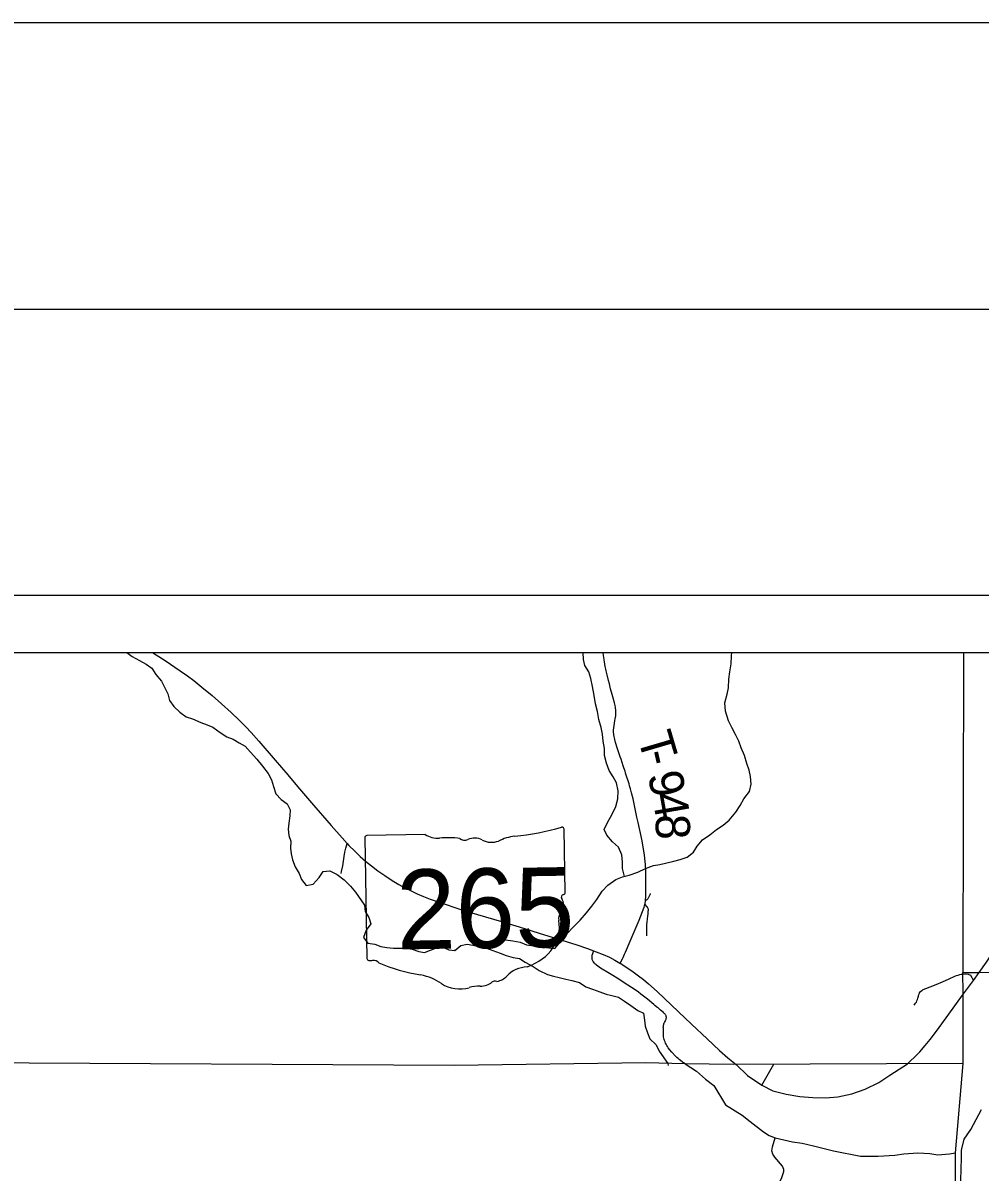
# Model space of a CAD drawing. Extents: x 0 to 2329303, y 0 to 694397.
# Drawn here: x 3.861 to 5.532, y 19.992 to 22 of the extents above; entities that cross this region are included whole.
import ezdxf

# ---------------------------------------------------------------- set-up
doc = ezdxf.new("R2010")
doc.units = 0
for name, color, linetype in [('GM_X_Minor_River', 7, 'Continuous'), ('GM_X_State_Route', 7, 'Continuous'), ('GM_X_State_Shield', 7, 'Continuous'), ('GM_X_Township', 7, 'Continuous'), ('GM_X_Township_Road', 7, 'Continuous'), ('GM_X_Township_Road_Text', 7, 'Continuous'), ('GM_X_Township_ROW', 7, 'Continuous'), ('SH_Border', 7, 'Continuous'), ('SH_Cut_Line', 7, 'Continuous'), ('SH_Data', 7, 'Continuous')]:
    doc.layers.add(name, color=color, linetype=linetype)

msp = doc.modelspace()

# ---------------------------------------------------------------- linework, layer by layer
at = {"layer": 'GM_X_Minor_River'}
for points in [[(4.0425, 20.9), (4.0521, 20.8932), (4.0647, 20.8863), (4.076, 20.8798), (4.0862, 20.8729), (4.0933, 20.8619), (4.1028, 20.8501), (4.1091, 20.8383), (4.1142, 20.8276), (4.1173, 20.8161), (4.1244, 20.8055), (4.1351, 20.7958), (4.1461, 20.7877), (4.1574, 20.784), (4.1715, 20.778), (4.1828, 20.7739), (4.1929, 20.7694), (4.2056, 20.7602), (4.217, 20.7525), (4.2283, 20.7484), (4.2384, 20.7423), (4.249, 20.7362), (4.2584, 20.726), (4.2696, 20.7135), (4.2795, 20.7014), (4.2894, 20.6889), (4.2953, 20.6778), (4.2988, 20.6659), (4.3028, 20.6532), (4.3118, 20.643), (4.3224, 20.6357), (4.3275, 20.6254), (4.327, 20.615), (4.3253, 20.6021)], [(4.6727, 20.3827), (4.6789, 20.3952), (4.6903, 20.4016), (4.704, 20.398), (4.7164, 20.3965), (4.7293, 20.3941), (4.7406, 20.3892), (4.7535, 20.3873), (4.7691, 20.3854), (4.79, 20.3832), (4.8012, 20.3956), (4.8108, 20.4083), (4.8224, 20.4207), (4.834, 20.4323), (4.8452, 20.4451), (4.8544, 20.4566), (4.8632, 20.4685), (4.8728, 20.4832), (4.8824, 20.4935), (4.8965, 20.5036), (4.9084, 20.508), (4.9199, 20.5112), (4.9349, 20.5161), (4.9483, 20.5225), (4.9625, 20.5278), (4.9732, 20.5297), (4.9855, 20.5325), (4.9978, 20.5357), (5.0089, 20.5385), (5.0208, 20.5425), (5.0321, 20.5513), (5.0386, 20.5619), (5.0478, 20.5726), (5.0607, 20.5818), (5.072, 20.5906), (5.0838, 20.5982), (5.0943, 20.6069), (5.1058, 20.6213), (5.1135, 20.6328), (5.1203, 20.6442), (5.1299, 20.6573), (5.1327, 20.6702), (5.1319, 20.6834), (5.1291, 20.6945), (5.1252, 20.706), (5.1211, 20.7199), (5.1155, 20.7333), (5.1111, 20.7452), (5.1056, 20.7566), (5.0992, 20.7692), (5.0932, 20.7806), (5.0879, 20.7976), (5.0871, 20.812), (5.091, 20.8273), (5.093, 20.8386), (5.0941, 20.8535), (5.0957, 20.8663), (5.0977, 20.8804), (5.0985, 20.894), (5.0988, 20.9)], [(4.9115, 20.5089), (4.9083, 20.5228), (4.9083, 20.534), (4.9067, 20.5468), (4.9011, 20.5598), (4.8904, 20.5695), (4.8805, 20.5807), (4.8762, 20.591), (4.8826, 20.604), (4.8894, 20.6166), (4.8965, 20.6313), (4.8997, 20.6446), (4.9004, 20.6582), (4.8976, 20.6725), (4.8917, 20.6828), (4.8849, 20.6937), (4.8801, 20.7068), (4.8765, 20.7199), (4.8765, 20.7323), (4.8745, 20.745), (4.8734, 20.7574), (4.8706, 20.7693), (4.8666, 20.7828), (4.8645, 20.7971), (4.8609, 20.8106), (4.8585, 20.8249), (4.856, 20.8405), (4.8527, 20.8544), (4.8492, 20.8663), (4.8424, 20.8772), (4.8401, 20.8876), (4.8393, 20.9), (4.8393, 20.9)], [(4.3253, 20.6021), (4.324, 20.5913), (4.3255, 20.5805), (4.329, 20.5702), (4.3285, 20.5581), (4.3296, 20.5481), (4.3318, 20.5378), (4.3362, 20.5255), (4.3437, 20.5141), (4.3476, 20.5034), (4.3558, 20.4928), (4.3682, 20.4955), (4.3783, 20.5067), (4.3852, 20.5173), (4.3971, 20.5184), (4.4101, 20.5124), (4.4219, 20.5031), (4.433, 20.4918), (4.4417, 20.4813), (4.4575, 20.4585), (4.459, 20.4477), (4.4653, 20.437), (4.4688, 20.4263), (4.4603, 20.4149), (4.4558, 20.4023), (4.4633, 20.3921), (4.4757, 20.3904), (4.4862, 20.3867), (4.4963, 20.3846), (4.5083, 20.3834), (4.5203, 20.3833), (4.5307, 20.3836), (4.5407, 20.3815), (4.5524, 20.3778), (4.5624, 20.3761), (4.5727, 20.38), (4.5834, 20.384), (4.5946, 20.3855), (4.6051, 20.3806), (4.6151, 20.3793), (4.6139, 20.3792)], [(4.6151, 20.3793), (4.6256, 20.3879), (4.6367, 20.3906), (4.6467, 20.3886), (4.6592, 20.3862), (4.6709, 20.3834), (4.6814, 20.3797), (4.6943, 20.3749), (4.7049, 20.3709), (4.717, 20.3672), (4.7282, 20.3652), (4.7384, 20.3591), (4.7522, 20.3516), (4.7624, 20.3443), (4.777, 20.3376), (4.7875, 20.3347), (4.7976, 20.3323), (4.8093, 20.3294), (4.8197, 20.327), (4.833, 20.3234), (4.8441, 20.3158), (4.8558, 20.3121), (4.8687, 20.307), (4.8796, 20.3033), (4.8897, 20.3008), (4.9014, 20.2976), (4.9116, 20.2908), (4.9226, 20.2831), (4.9349, 20.2747), (4.945, 20.2702), (4.9466, 20.2579), (4.9477, 20.2475), (4.9517, 20.2356), (4.956, 20.225), (4.9671, 20.2145), (4.9719, 20.2035), (4.9875, 20.1818), (4.988, 20.1784)]]:
    msp.add_lwpolyline(points, dxfattribs=at)
at = {"layer": 'GM_X_State_Route'}
for points in [[(4.0875, 20.9), (4.0936, 20.8963), (4.1095, 20.8859), (4.1355, 20.8681), (4.1483, 20.8591), (4.1593, 20.8509), (4.1737, 20.8394), (4.1913, 20.8247), (4.2076, 20.8106), (4.2246, 20.7951), (4.2389, 20.7816), (4.2504, 20.77), (4.2594, 20.7604), (4.2729, 20.7453), (4.3017, 20.7121), (4.3235, 20.6863)], [(4.3235, 20.6863), (4.3407, 20.666), (4.3649, 20.6375), (4.3991, 20.5977), (4.4183, 20.5761), (4.4271, 20.5665), (4.4303, 20.5631), (4.4405, 20.5527), (4.45, 20.5437), (4.4594, 20.5354), (4.4696, 20.5271), (4.4806, 20.5188), (4.493, 20.5102), (4.5057, 20.502), (4.5175, 20.4948), (4.5267, 20.4897), (4.5379, 20.484), (4.5498, 20.4784), (4.5606, 20.4737), (4.5723, 20.4692), (4.5896, 20.4631), (4.624, 20.4519), (4.6409, 20.4465), (4.6968, 20.43), (4.7276, 20.4205), (4.7628, 20.4099), (4.7947, 20.4), (4.8284, 20.3893), (4.8471, 20.3829), (4.8576, 20.379), (4.8624, 20.3772), (4.8745, 20.3723), (4.8853, 20.3675), (4.8946, 20.3628), (4.9036, 20.3575), (4.904, 20.3573), (4.9141, 20.3509), (4.9265, 20.3423), (4.936, 20.3354), (4.9448, 20.3286), (4.9538, 20.3211), (4.9684, 20.3079), (5.0061, 20.2724), (5.0288, 20.2506), (5.0559, 20.2248), (5.0775, 20.2047), (5.0922, 20.1916), (5.1065, 20.18)], [(5.5019, 20.3015), (5.5211, 20.327), (5.5308, 20.3409), (5.5439, 20.3593), (5.5686, 20.3975), (5.6124, 20.4489), (5.6569, 20.5022), (5.6914, 20.5425), (5.7219, 20.5802), (5.7635, 20.6292)], [(5.4059, 20.1814), (5.4095, 20.1848), (5.4199, 20.1949), (5.4272, 20.2025), (5.4367, 20.2134), (5.4455, 20.2241), (5.4563, 20.2382), (5.4779, 20.268), (5.5019, 20.3015)], [(5.1065, 20.18), (5.1265, 20.1609), (5.1512, 20.1442), (5.1705, 20.1342), (5.194, 20.1283), (5.2177, 20.1243), (5.2406, 20.1224), (5.2627, 20.122), (5.2842, 20.124), (5.3084, 20.1289), (5.3317, 20.1374), (5.3557, 20.1487), (5.3749, 20.1618), (5.4059, 20.1814)], [(5.5007, 20.033), (5.5046, 20.0496), (5.5164, 20.0666), (5.5349, 20.1016)], [(5.4896, 19.5547), (5.4963, 19.5711), (5.5005, 19.5907), (5.503, 19.6107), (5.5027, 19.6294), (5.5009, 19.6616), (5.5008, 19.6926), (5.4982, 19.7527), (5.4993, 19.8307), (5.4998, 19.9151), (5.4988, 19.9776), (5.5001, 20.0174), (5.4999, 20.0298), (5.5007, 20.033)]]:
    msp.add_lwpolyline(points, dxfattribs=at)
at = {"layer": 'GM_X_State_Shield'}
for p, q in [((4.5636, 20.5821), (4.4617, 20.5803)), ((4.808, 20.4808), (4.8061, 20.5914)), ((4.4583, 20.5766), (4.4619, 20.3654)), ((4.808, 20.4809), (4.808, 20.4808))]:
    msp.add_line(p, q, dxfattribs=at)
for centre, major_axis, start_param, end_param in [((4.4623, 20.5772), (0.00403, 0.00007), 1.712693, 3.28349), ((4.5874, 20.607), (0.0391, 0.0007), 4.042523, 4.731795), ((4.7304, 20.5203), (0.0742, 0.0012), 1.699011, 2.107814), ((4.6774, 20.8721), (0.369, 0.0062), 4.814394, 5.042369), ((4.8023, 20.5918), (0.00387, 0.00006), 6.141152, 7.989035), ((4.6028, 20.4641), (0.1404, 0.0024), 1.404758, 1.657858), ((4.6327, 20.5811), (0.0113, 0.0002), 3.836095, 5.185415), ((4.6497, 20.557), (0.0235, 0.0004), 0.950623, 2.079405), ((4.6794, 20.591), (0.0282, 0.0005), 4.081561, 5.145723), ((4.8039, 20.4803), (0.00415, 0.00007), 5.05454, 6.418171), ((4.8072, 20.4727), (0.006, 0.0001), 1.883978, 3.671073), ((4.7693, 20.4581), (0.036, 0.0006), 5.934695, 6.695948), ((4.8227, 20.4348), (0.0262, 0.0004), 2.387724, 3.262537), ((4.7057, 20.4188), (0.0923, 0.0015), 5.101752, 6.440018), ((4.4659, 20.365), (0.00407, 0.00007), 3.00124, 4.508301), ((4.4661, 20.3866), (0.031, 0.0005), 4.665946, 4.897461), ((4.473, 20.3533), (0.0112, 0.0002), 0.519207, 1.627899), ((4.6112, 20.5456), (0.2665, 0.0045), 4.195997, 4.488961), ((4.7465, 20.3108), (0.0506, 0.0008), 1.647645, 2.488434), ((4.5363, 20.2716), (0.0834, 0.0014), 0.823519, 1.323587), ((4.6251, 20.3548), (0.0529, 0.0009), 4.026481, 4.996735), ((4.6569, 20.2823), (0.0435, 0.0007), 1.495662, 1.94098), ((4.6598, 20.3396), (0.0282, 0.0005), 4.691044, 5.507374), ((4.6856, 20.3196), (0.00794, 0.00013), 1.147584, 2.315152), ((4.6818, 20.3486), (0.0298, 0.0005), 4.937069, 5.64225)]:
    msp.add_ellipse(centre, major_axis=major_axis, ratio=0.8, start_param=start_param, end_param=end_param, dxfattribs=at)
at = {"layer": 'GM_X_Township'}
msp.add_line((5.5036, 20.9), (5.5027, 20.3409), dxfattribs=at)
for points in [[(5.8223, 14.1123), (5.5, 14.1), (5.5092, 14.6075), (5.4849, 16.2502), (5.4862, 16.3702), (5.4966, 17.3083), (5.484, 18.4012), (5.4927, 19.2711), (5.4941, 19.3381), (5.4896, 19.5547), (5.4893, 19.9096), (5.4898, 20.0261), (5.5032, 20.182), (5.5028, 20.3048), (5.5027, 20.3409), (5.5308, 20.3409), (5.6417, 20.3416)], [(5.5032, 20.182), (5.102, 20.1805), (5.0168, 20.1816), (4.9486, 20.1829), (4.6141, 20.1787), (3.7653, 20.1833), (2.7861, 20.1837), (2.2689, 20.1812), (2.1, 20.1819)]]:
    msp.add_lwpolyline(points, dxfattribs=at)
at = {"layer": 'GM_X_Township_Road'}
for points in [[(4.9483, 20.4669), (4.9487, 20.4742), (4.9489, 20.4827), (4.9491, 20.4991), (4.9491, 20.5103), (4.9488, 20.5214), (4.9485, 20.526), (4.9482, 20.5299), (4.9471, 20.5402), (4.9463, 20.5466), (4.9447, 20.5562), (4.9422, 20.571), (4.9395, 20.5845), (4.9384, 20.5897), (4.9353, 20.6031), (4.9333, 20.6121), (4.9296, 20.6301), (4.9265, 20.6442), (4.924, 20.655), (4.9222, 20.6619), (4.9205, 20.6674), (4.9197, 20.6704), (4.9185, 20.6741), (4.9174, 20.6778), (4.9165, 20.6803), (4.9152, 20.6839), (4.914, 20.6875), (4.9134, 20.6894), (4.9125, 20.6925), (4.9115, 20.6956), (4.9105, 20.6987), (4.9095, 20.7018), (4.9056, 20.7136), (4.9041, 20.7179), (4.8995, 20.7315), (4.8959, 20.7428), (4.8946, 20.7478), (4.8932, 20.7562), (4.8927, 20.7614), (4.8926, 20.7646), (4.8935, 20.7724), (4.8949, 20.7808), (4.8955, 20.784), (4.8962, 20.7892), (4.8966, 20.7944), (4.8965, 20.799), (4.8959, 20.8042), (4.8953, 20.8073), (4.8941, 20.8123), (4.8913, 20.8224), (4.889, 20.8306), (4.8886, 20.8325), (4.8874, 20.8369), (4.8852, 20.8451), (4.8837, 20.8514), (4.8812, 20.8609), (4.8795, 20.8679), (4.8788, 20.8711), (4.8779, 20.8756), (4.8765, 20.8839), (4.876, 20.8872), (4.8753, 20.8917), (4.875, 20.8943), (4.8742, 20.9)], [(4.4167, 20.5138), (4.4176, 20.5176), (4.4195, 20.5273), (4.4219, 20.5435), (4.4233, 20.5513), (4.4251, 20.5583), (4.4271, 20.5665)], [(4.9483, 20.4669), (4.9492, 20.4673), (4.9497, 20.4676), (4.9502, 20.4679), (4.9507, 20.4682), (4.9513, 20.4688), (4.9518, 20.4693), (4.9524, 20.4699), (4.953, 20.4707), (4.9535, 20.4716), (4.957, 20.4786), (4.9573, 20.4792)], [(4.904, 20.3573), (4.9079, 20.3647), (4.9091, 20.367), (4.9119, 20.3729), (4.9135, 20.3765), (4.9218, 20.3958), (4.9268, 20.4079), (4.9335, 20.4241), (4.9372, 20.4325), (4.9403, 20.4402), (4.9431, 20.4475), (4.9457, 20.4552), (4.9465, 20.4576), (4.9472, 20.4603)], [(4.9472, 20.4603), (4.9476, 20.4618), (4.9482, 20.4657), (4.9483, 20.4669)], [(4.9509, 20.4048), (4.9508, 20.4058), (4.9507, 20.4074), (4.9504, 20.414), (4.9504, 20.4185), (4.9507, 20.4243), (4.9512, 20.4295), (4.9517, 20.434), (4.9524, 20.4398), (4.9528, 20.4429), (4.9529, 20.4441), (4.9532, 20.4479), (4.9533, 20.45), (4.9533, 20.4513), (4.9531, 20.4521), (4.9528, 20.453), (4.9524, 20.4539), (4.9519, 20.4547), (4.9516, 20.4553), (4.9511, 20.4559), (4.9472, 20.4603)], [(4.8915, 20.3356), (4.8855, 20.3393), (4.8698, 20.3488), (4.8649, 20.3522), (4.863, 20.3537), (4.8613, 20.355), (4.86, 20.3562), (4.859, 20.3574), (4.8571, 20.36), (4.8564, 20.3612), (4.8559, 20.3623), (4.8554, 20.3635), (4.8551, 20.3647), (4.855, 20.3656), (4.8549, 20.3673), (4.8551, 20.3695), (4.8554, 20.3713), (4.8562, 20.3744), (4.8572, 20.3778), (4.8576, 20.379)], [(5.4175, 20.2842), (5.4186, 20.2855), (5.4201, 20.2873), (5.4216, 20.2894), (5.4224, 20.2912), (5.4232, 20.2938), (5.424, 20.2962), (5.4246, 20.2981), (5.425, 20.2994), (5.4252, 20.3006), (5.4255, 20.3019), (5.4258, 20.3028), (5.4261, 20.3037), (5.4266, 20.3046), (5.427, 20.3055), (5.4287, 20.3075), (5.4306, 20.3093), (5.4319, 20.3102), (5.4333, 20.3112), (5.4347, 20.3119), (5.4363, 20.3126), (5.4379, 20.3132), (5.4455, 20.3158), (5.4559, 20.3198), (5.4667, 20.3245), (5.4785, 20.33), (5.4884, 20.3344), (5.4914, 20.3355), (5.4943, 20.3365), (5.4971, 20.3373), (5.4997, 20.3379), (5.5018, 20.3383)], [(5.5018, 20.3383), (5.5068, 20.3385), (5.5117, 20.3379), (5.5156, 20.3362), (5.5211, 20.327)], [(5.0173, 20.1814), (5.0149, 20.1831), (5.0128, 20.1846), (5.0094, 20.1872), (5.0071, 20.189), (5.0052, 20.1906), (5.003, 20.1926), (5.0005, 20.195), (4.9942, 20.2017), (4.99, 20.2067), (4.9879, 20.2094), (4.9866, 20.2115), (4.9853, 20.2135), (4.9842, 20.2155), (4.9832, 20.2176), (4.9824, 20.2196), (4.9817, 20.2219), (4.9811, 20.224), (4.9805, 20.226), (4.98, 20.2286), (4.9798, 20.231), (4.9796, 20.2337), (4.9795, 20.2416), (4.9795, 20.2433), (4.9794, 20.2449), (4.9795, 20.246), (4.9795, 20.2472), (4.9797, 20.2483), (4.9799, 20.2494), (4.9802, 20.2503), (4.9806, 20.2516), (4.981, 20.2525), (4.9815, 20.2536), (4.983, 20.2565), (4.9834, 20.2574), (4.9838, 20.2582), (4.9843, 20.2595), (4.9846, 20.2606), (4.9847, 20.2616), (4.9847, 20.2627), (4.9845, 20.2638), (4.9842, 20.265), (4.9837, 20.2662), (4.9831, 20.2672), (4.9824, 20.2681), (4.9817, 20.2691), (4.9806, 20.2702), (4.9795, 20.2713), (4.9747, 20.2754), (4.9703, 20.279), (4.9682, 20.2807), (4.9647, 20.2836), (4.9627, 20.2853), (4.9516, 20.2945), (4.9402, 20.3033), (4.9359, 20.3066), (4.9302, 20.3106), (4.9177, 20.3191), (4.8989, 20.3311), (4.8915, 20.3356)], [(5.0173, 20.1814), (5.0374, 20.1687), (5.0532, 20.1546), (5.0677, 20.1435), (5.0878, 20.1099), (5.1172, 20.092), (5.1308, 20.0809), (5.1542, 20.0624), (5.164, 20.0563), (5.1748, 20.0519), (5.2051, 20.0452), (5.222, 20.043), (5.2414, 20.038), (5.2768, 20.0292), (5.3235, 20.0203), (5.3547, 20.0201), (5.3839, 20.0219), (5.3994, 20.0244), (5.4237, 20.026), (5.4446, 20.0247), (5.459, 20.0227), (5.4794, 20.0242), (5.4898, 20.0261)], [(5.2134, 19.9026), (5.2133, 19.9029), (5.213, 19.9036), (5.21, 19.9091), (5.2071, 19.913), (5.2038, 19.9149), (5.1898, 19.9169), (5.1861, 19.9188), (5.1791, 19.9265), (5.173, 19.94), (5.1719, 19.9484), (5.1748, 19.9597), (5.1856, 19.9813), (5.1897, 19.993), (5.1899, 19.997), (5.1873, 20.0026), (5.174, 20.0186), (5.1706, 20.0237), (5.1688, 20.0296), (5.1702, 20.0365), (5.1748, 20.0519)]]:
    msp.add_lwpolyline(points, dxfattribs=at)
at = {"layer": 'GM_X_Township_ROW'}
msp.add_lwpolyline([(5.1512, 20.1442), (5.1726, 20.1808)], dxfattribs=at)
at = {"layer": 'SH_Border'}
msp.add_lwpolyline([(1.5, 21.5), (33.5, 21.5), (33.5, 0.5), (1.5, 0.5)], close=True, dxfattribs=at)
at = {"layer": 'SH_Cut_Line'}
msp.add_lwpolyline([(0, 0), (34, 0), (34, 22), (0, 22)], close=True, dxfattribs=at)
at = {"layer": 'SH_Data'}
for points in [[(2, 21), (9, 21), (9, 14), (2, 14)], [(2.1, 20.9), (8.9, 20.9), (8.9, 14.1), (2.1, 14.1)]]:
    msp.add_lwpolyline(points, close=True, dxfattribs=at)

# ---------------------------------------------------------------- texts
at = {"layer": 'GM_X_State_Shield'}
msp.add_text('265', height=0.13922, rotation=0.961, dxfattribs=at).set_placement((4.5143, 20.3811))
at = {"layer": 'GM_X_Township_Road_Text'}
for s, rotation, p in [('T', 286.4172, (4.9337, 20.7525)), ('-', 283.0242, (4.9434, 20.7246)), ('9', 282.2005, (4.9517, 20.6866)), ('4', 279.9648, (4.9594, 20.6511)), ('8', 271.622, (4.9655, 20.6169))]:
    msp.add_text(s, height=0.06, rotation=rotation, dxfattribs=at).set_placement(p)

doc.saveas('drawing.dxf')
